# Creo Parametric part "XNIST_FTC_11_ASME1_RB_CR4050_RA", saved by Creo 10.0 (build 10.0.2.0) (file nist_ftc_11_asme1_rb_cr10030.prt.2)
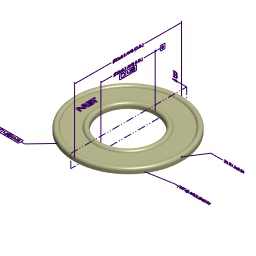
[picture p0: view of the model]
Units: millimeter Kilogram Sec (mmKs); MM, KILOGRAM, SECS

Other parameters: D15, OUTSIDE_CIRCLE_ARCLENGTH

Created from: NIST_FTC_11_ASME1_RB_CR4050_RA.PRT

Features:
  1. datum plane "RIGHT"
  2. datum plane "TOP"
  3. datum plane "FRONT"
  4. coordinate system
  5. imported feature
  6. curve
  7. curve
  8. datum axis
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
Other named items: CS0, DRF_AB, AD15, SYMBOL_2, AD55, AD57, GP4, AD62, GP5, NOTE_9, DATUM_TAG_B, NOTE_10, AD73, GP6, GP7, NOTE_14, DATUM_TAG_A, MBD_A, MBD_B, ANNOT_LAYER_STATE0001, ANNOT_LAYER_STATE0002

Layers: ALL_ANNOTATIONS, ALL_AXES, ALL_CSYS, ALL_CURVES, ALL_PLANES, ALL_POINTS, ALL_QUILTS, DEF_CSYS, DEF_PLANES

Notes: 2X R0.1 MAX | �⌖ | 0.01

Surfaces: 8 torus, 4 cylinder, 2 plane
